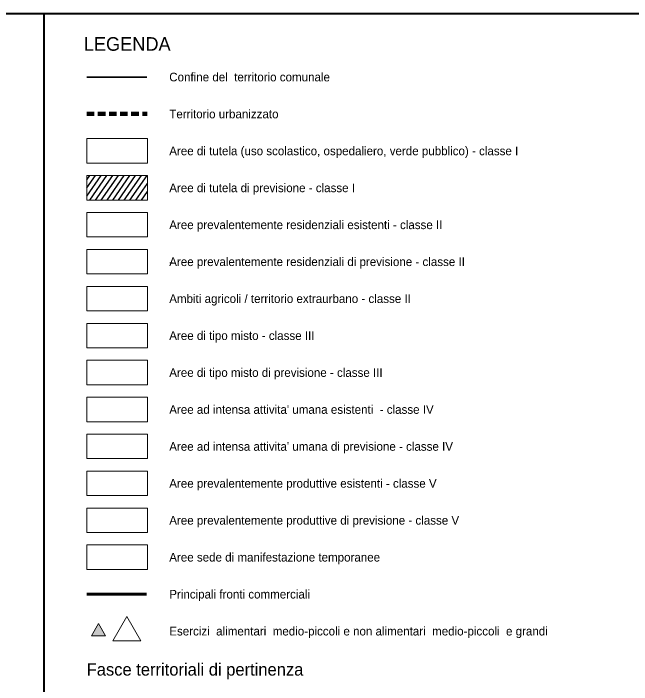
# Model space of a CAD drawing. Extents: x 654952 to 658955, y 890426 to 894481.
# Drawn here: x 655953 to 656954, y 893394 to 894481 of the extents above; entities that cross this region are included whole.
import ezdxf

# ---------------------------------------------------------------- set-up
doc = ezdxf.new("R2010")
doc.units = 0
doc.header["$LTSCALE"] = 4
doc.linetypes.add('MEDIUM_DASHED', pattern=[4.5, 3, -1.5])
doc.layers.add('60', color=7, linetype='Continuous', lineweight=35)

msp = doc.modelspace()

# ---------------------------------------------------------------- hatches: boundary and pattern name
at = {"layer": '60'}
msp.add_hatch(color=256, dxfattribs=at).paths.add_polyline_path([(656090.61, 893493.12), (656101.98, 893473.44), (656079.23, 893473.44)])

# ---------------------------------------------------------------- linework, layer by layer
at = {"layer": '60', "lineweight": 40}
msp.add_line((656002.15, 894480.73), (657055.17, 894480.74), dxfattribs=at)
at = {"layer": '60'}
msp.add_line((656071.82, 894377.81), (656168.8, 894377.81), dxfattribs=at)
at = {"layer": '60', "linetype": 'MEDIUM_DASHED', "lineweight": 90}
msp.add_line((656071.83, 894318), (656169.49, 894318), dxfattribs=at)
at = {"layer": '60', "lineweight": 25}
for p, q in [((656071.83, 894211.47), (656076.54, 894218.2)), ((656071.83, 894198.22), (656085.82, 894218.2)), ((656071.83, 894184.97), (656095.1, 894218.2)), ((656076.68, 894178.6), (656104.4, 894218.2)), ((656085.96, 894178.6), (656113.68, 894218.2)), ((656095.23, 894178.6), (656122.95, 894218.2)), ((656104.51, 894178.6), (656132.23, 894218.2)), ((656113.8, 894178.6), (656141.52, 894218.2)), ((656123.07, 894178.6), (656150.79, 894218.2)), ((656132.34, 894178.6), (656160.06, 894218.2)), ((656141.64, 894178.6), (656169.36, 894218.2)), ((656150.92, 894178.6), (656169.75, 894205.52)), ((656160.2, 894178.6), (656169.75, 894192.22)), ((656169.48, 894178.6), (656169.75, 894178.97))]:
    msp.add_line(p, q, dxfattribs=at)
at = {"layer": '60', "lineweight": 60}
msp.add_line((656168.41, 893540.62), (656071.83, 893540.62), dxfattribs=at)
at = {"layer": '60', "lineweight": 40}
msp.add_lwpolyline([(656002.16, 894480.73), (656002.16, 892994.48), (654952.16, 892994.48), (654952.16, 894480.73)], close=True, dxfattribs=at)
at = {"layer": '60', "lineweight": 13}
for points in [[(656071.83, 894278), (656169.75, 894278), (656169.75, 894238.4), (656071.83, 894238.4)], [(656071.83, 894218.2), (656169.75, 894218.2), (656169.75, 894178.6), (656071.83, 894178.6)], [(656071.83, 894158.42), (656169.75, 894158.42), (656169.75, 894118.82), (656071.83, 894118.82)], [(656071.83, 894098.62), (656169.75, 894098.62), (656169.75, 894059.02), (656071.83, 894059.02)], [(656071.83, 894038.85), (656169.75, 894038.85), (656169.75, 893999.25), (656071.83, 893999.25)], [(656071.83, 893979.02), (656169.75, 893979.02), (656169.75, 893939.42), (656071.83, 893939.42)], [(656071.83, 893919.22), (656169.75, 893919.22), (656169.75, 893879.62), (656071.83, 893879.62)], [(656071.83, 893859.42), (656169.75, 893859.42), (656169.75, 893819.82), (656071.83, 893819.82)], [(656071.83, 893799.62), (656169.75, 893799.62), (656169.75, 893760.02), (656071.83, 893760.02)], [(656071.83, 893739.82), (656169.75, 893739.82), (656169.75, 893700.22), (656071.83, 893700.22)], [(656071.83, 893680.02), (656169.75, 893680.02), (656169.75, 893640.42), (656071.83, 893640.42)], [(656071.83, 893620.25), (656169.75, 893620.25), (656169.75, 893580.65), (656071.83, 893580.65)], [(656136.54, 893504.43), (656159.28, 893465.05), (656113.81, 893465.05)], [(656090.61, 893493.12), (656101.98, 893473.44), (656079.23, 893473.44)]]:
    msp.add_lwpolyline(points, close=True, dxfattribs=at)

# ---------------------------------------------------------------- texts
at = {"layer": '60'}
for s, height, p in [('LEGENDA', 22, (656066.88, 894420.33)), ('Confine del  territorio comunale  ', 14, (656205.23, 894370.76)), ('Territorio urbanizzato', 14, (656205.23, 894310.98)), ('Aree di tutela (uso scolastico, ospedaliero, verde pubblico) - classe I', 14, (656205.23, 894251.16)), ('Aree di tutela di previsione - classe I', 14, (656205.23, 894191.36)), ('Aree prevalentemente residenziali esistenti - classe II', 14, (656205.23, 894131.58)), ('Aree prevalentemente residenziali di previsione - classe II', 14, (656205.23, 894071.78)), ('-', 14.06, (656205.23, 894071.75)), ('Ambiti agricoli / territorio extraurbano - classe II', 14, (656205.23, 894012.01)), ('Aree di tipo misto - classe III', 14, (656205.23, 893952.18)), ('Aree di tipo misto di previsione - classe III', 14, (656205.23, 893892.38)), ("Aree ad intensa attivita' umana esistenti  - classe IV", 14, (656205.23, 893832.58)), ("Aree ad intensa attivita' umana di previsione - classe IV", 14, (656205.23, 893772.78)), ('Aree prevalentemente produttive esistenti - classe V', 14, (656205.23, 893712.98)), ('Aree prevalentemente produttive di previsione - classe V', 14, (656205.23, 893653.18)), ('Aree sede di manifestazione temporanee', 14, (656205.23, 893593.41)), ('Principali fronti commerciali', 14, (656205.23, 893533.58)), ('Esercizi  alimentari  medio-piccoli e non alimentari  medio-piccoli  e grandi', 14, (656205.23, 893473.78)), ('Fasce territoriali di pertinenza', 20, (656071.53, 893408.8))]:
    msp.add_text(s, height=height, dxfattribs=at).set_placement(p)

doc.saveas('drawing.dxf')
